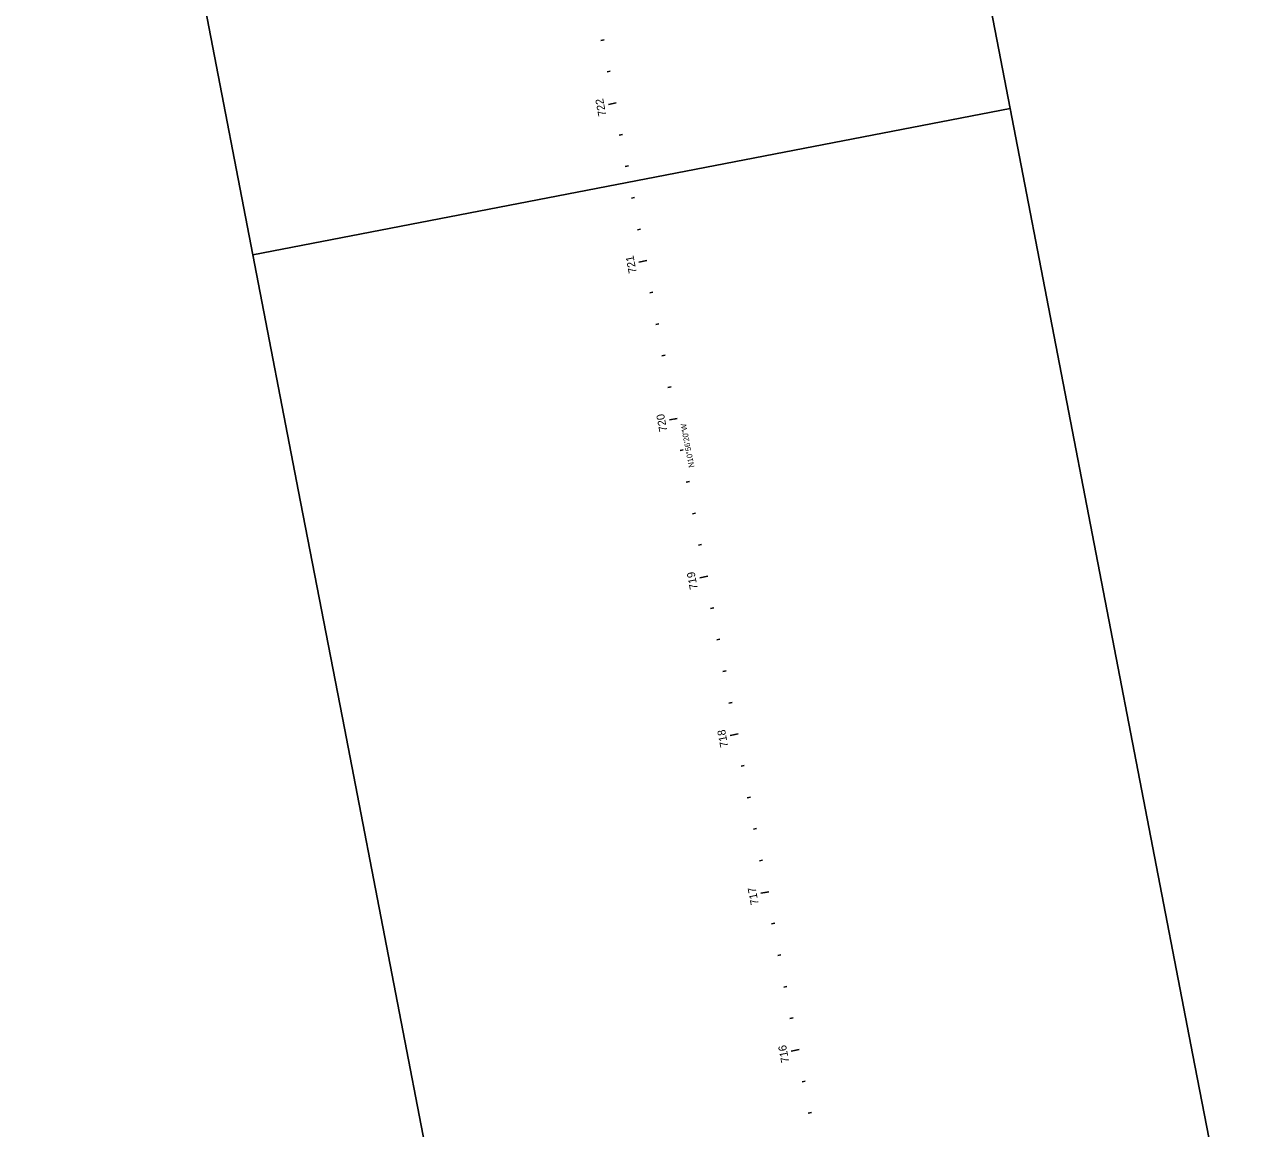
# Model space of a CAD drawing. Extents: x 2005381 to 2007040, y 402385 to 405116.
# Drawn here: x 2005381 to 2006136, y 403745 to 404432 of the extents above; entities that cross this region are included whole.
import ezdxf

# ---------------------------------------------------------------- set-up
doc = ezdxf.new("R2010")
doc.units = 0
for name, color, linetype in [('ClipDrawingBound_dp', 7, 'Continuous'), ('TextAlgnStation100', 7, 'Continuous'), ('TextAlgnStation1000', 7, 'Continuous'), ('TextAlgnStation500', 7, 'Continuous'), ('TextAlgnTangent', 7, 'Continuous'), ('TextAlgnTicks100', 7, 'Continuous'), ('TextAlgnTicks1000', 7, 'Continuous'), ('TextAlgnTicks500', 7, 'Continuous'), ('TextAlgnTicks5000', 7, 'Continuous')]:
    doc.layers.add(name, color=color, linetype=linetype)

msp = doc.modelspace()

# ---------------------------------------------------------------- linework, layer by layer
at = {"layer": 'ClipDrawingBound_dp'}
for points in [[(2005522.84, 404288.61), (2005994.12, 404379.7), (2005965.66, 404526.97), (2005937.19, 404674.24), (2005908.73, 404821.52), (2005880.27, 404968.79), (2005851.8, 405116.07), (2005380.52, 405024.98), (2005408.99, 404877.71), (2005437.45, 404730.43), (2005465.92, 404583.16), (2005494.38, 404435.88)], [(2005665.17, 403552.24), (2006136.44, 403643.32), (2006107.98, 403790.6), (2006079.52, 403937.87), (2006051.05, 404085.15), (2006022.59, 404232.42), (2005994.12, 404379.7), (2005522.84, 404288.61), (2005551.31, 404141.33), (2005579.77, 403994.06), (2005608.24, 403846.79), (2005636.7, 403699.51)]]:
    msp.add_lwpolyline(points, close=True, dxfattribs=at)
at = {"layer": 'TextAlgnTicks100'}
for p, q in [((2005741.41, 404422.52), (2005739.44, 404422.14)), ((2005745.2, 404402.88), (2005743.24, 404402.5)), ((2005749, 404383.24), (2005744.09, 404382.3)), ((2005752.79, 404363.61), (2005750.83, 404363.23)), ((2005756.59, 404343.97), (2005754.62, 404343.59)), ((2005760.38, 404324.33), (2005758.42, 404323.95)), ((2005764.18, 404304.7), (2005762.21, 404304.32)), ((2005767.97, 404285.06), (2005763.06, 404284.11)), ((2005771.77, 404265.42), (2005769.8, 404265.04)), ((2005775.56, 404245.79), (2005773.6, 404245.41)), ((2005779.36, 404226.15), (2005777.39, 404225.77)), ((2005783.15, 404206.51), (2005781.19, 404206.13)), ((2005786.95, 404186.88), (2005782.04, 404185.93)), ((2005790.74, 404167.24), (2005788.78, 404166.86)), ((2005794.54, 404147.6), (2005792.58, 404147.23)), ((2005798.33, 404127.97), (2005796.37, 404127.59)), ((2005802.13, 404108.33), (2005800.17, 404107.95)), ((2005805.92, 404088.69), (2005801.02, 404087.75)), ((2005809.72, 404069.06), (2005807.76, 404068.68)), ((2005813.51, 404049.42), (2005811.55, 404049.04)), ((2005817.31, 404029.78), (2005815.35, 404029.41)), ((2005821.11, 404010.15), (2005819.14, 404009.77)), ((2005824.9, 403990.51), (2005819.99, 403989.56)), ((2005828.7, 403970.88), (2005826.73, 403970.5)), ((2005832.49, 403951.24), (2005830.53, 403950.86)), ((2005836.29, 403931.6), (2005834.32, 403931.22)), ((2005840.08, 403911.97), (2005838.12, 403911.59)), ((2005843.88, 403892.33), (2005838.97, 403891.38)), ((2005847.67, 403872.69), (2005845.71, 403872.31)), ((2005851.47, 403853.06), (2005849.5, 403852.68)), ((2005855.26, 403833.42), (2005853.3, 403833.04)), ((2005859.06, 403813.78), (2005857.09, 403813.4)), ((2005862.85, 403794.15), (2005857.94, 403793.2)), ((2005866.65, 403774.51), (2005864.68, 403774.13)), ((2005870.44, 403754.87), (2005868.48, 403754.49))]:
    msp.add_line(p, q, dxfattribs=at)
at = {"layer": 'TextAlgnTicks1000'}
for p, q in [((2005749, 404383.24), (2005747.03, 404382.86)), ((2005786.95, 404186.88), (2005782.04, 404185.93)), ((2005824.9, 403990.51), (2005822.94, 403990.13)), ((2005862.85, 403794.15), (2005860.89, 403793.77))]:
    msp.add_line(p, q, dxfattribs=at)
at = {"layer": 'TextAlgnTicks500'}
for p, q in [((2005749, 404383.24), (2005747.03, 404382.86)), ((2005767.97, 404285.06), (2005766.01, 404284.68)), ((2005786.95, 404186.88), (2005782.04, 404185.93)), ((2005805.92, 404088.69), (2005803.96, 404088.32)), ((2005824.9, 403990.51), (2005822.94, 403990.13)), ((2005843.88, 403892.33), (2005841.91, 403891.95)), ((2005862.85, 403794.15), (2005860.89, 403793.77))]:
    msp.add_line(p, q, dxfattribs=at)
at = {"layer": 'TextAlgnTicks5000'}
msp.add_line((2005786.95, 404186.88), (2005784.98, 404186.5), dxfattribs=at)

# ---------------------------------------------------------------- texts
at = {"layer": 'TextAlgnStation100'}
for s, p in [('722', (2005742.88, 404375.38)), ('721', (2005761.77, 404277.64)), ('720', (2005780.82, 404179.08)), ('719', (2005799.8, 404080.88)), ('718', (2005818.78, 403982.66)), ('717', (2005837.74, 403884.58)), ('716', (2005856.72, 403786.33))]:
    msp.add_text(s, height=4.98, rotation=100.93889, dxfattribs=at).set_placement(p)
at = {"layer": 'TextAlgnStation1000'}
msp.add_text('720', height=4.98, rotation=100.93889, dxfattribs=at).set_placement((2005780.82, 404179.08))
at = {"layer": 'TextAlgnStation500'}
msp.add_text('720', height=4.98, rotation=100.93889, dxfattribs=at).set_placement((2005780.82, 404179.08))
at = {"layer": 'TextAlgnTangent'}
msp.add_text('N10°56\'20"W', height=3.48, rotation=100.93889, dxfattribs=at).set_placement((2005797.67, 404156.68))

doc.saveas('drawing.dxf')
